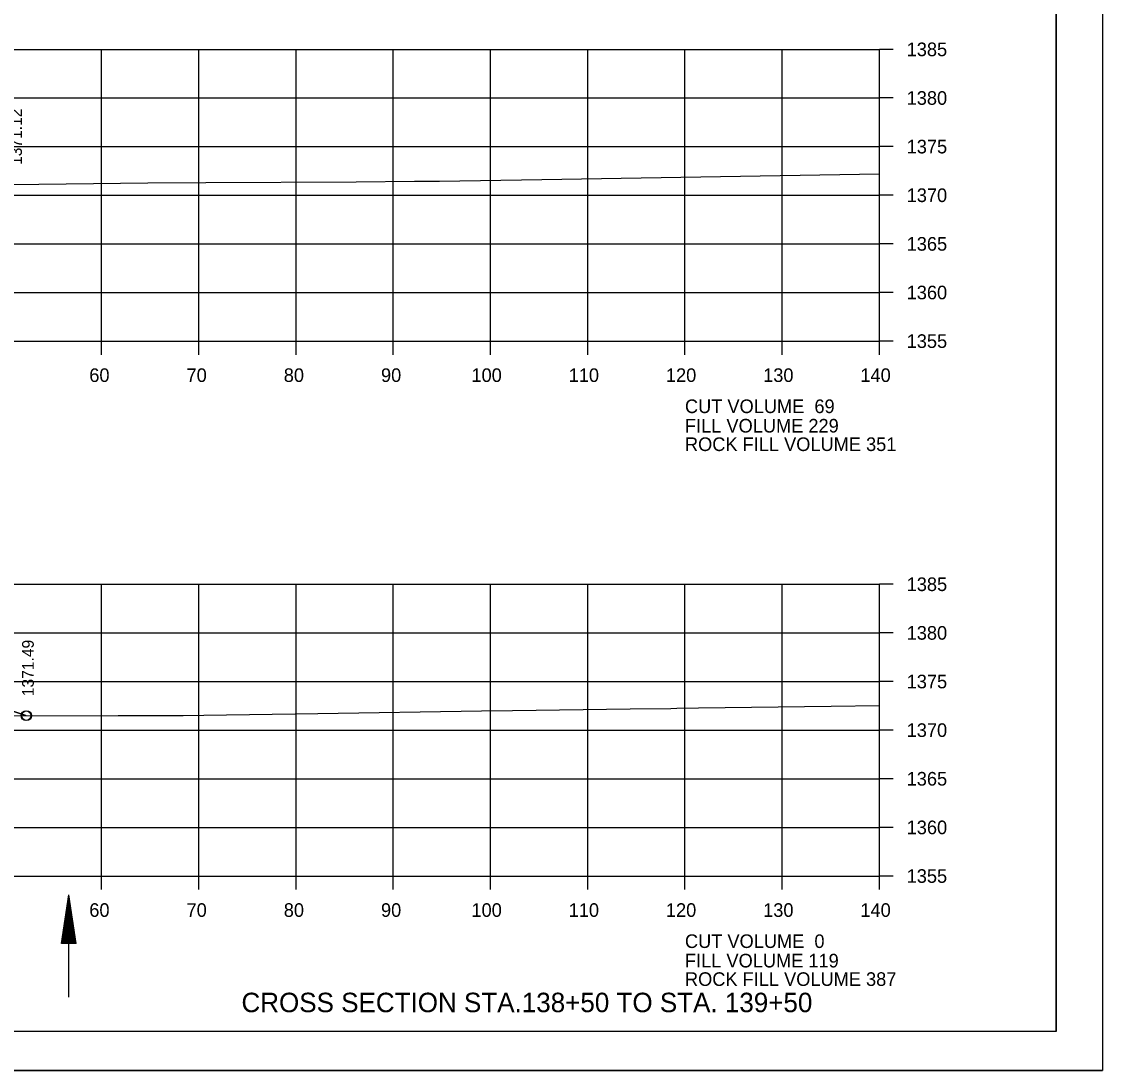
# Model space of a CAD drawing. Extents: x 1374311 to 1383814, y 384102 to 406278.
# Drawn here: x 1381680.4 to 1381791.6, y 389018 to 389125.9 of the extents above; entities that cross this region are included whole.
import ezdxf

# ---------------------------------------------------------------- set-up
doc = ezdxf.new("R2010")
doc.units = 0
for name, color, linetype in [('R_Axis', 7, 'Continuous'), ('R_Axis Annot', 7, 'Continuous'), ('R_Border', 7, 'Continuous'), ('R_Draft', 7, 'Continuous'), ('R_Exist Surface', 7, 'Continuous'), ('R_Fin Surface', 7, 'Continuous'), ('R_Grid', 7, 'Continuous'), ('R_No Plot', 7, 'Continuous'), ('R_Water', 7, 'Continuous'), ('R_Xsect Elev', 7, 'Continuous')]:
    doc.layers.add(name, color=color, linetype=linetype)

msp = doc.modelspace()

# ---------------------------------------------------------------- linework, layer by layer
at = {"layer": 'R_Axis'}
for p, q in [((1381768.66, 389093.02), (1381768.66, 389123.02)), ((1381770.06, 389123.02), (1381768.66, 389123.02)), ((1381770.06, 389118.02), (1381768.66, 389118.02)), ((1381770.06, 389113.02), (1381768.66, 389113.02)), ((1381770.06, 389108.02), (1381768.66, 389108.02)), ((1381770.06, 389103.02), (1381768.66, 389103.02)), ((1381770.06, 389098.02), (1381768.66, 389098.02)), ((1381488.66, 389093.02), (1381768.66, 389093.02)), ((1381688.66, 389091.62), (1381688.66, 389093.02)), ((1381698.66, 389091.62), (1381698.66, 389093.02)), ((1381708.66, 389091.62), (1381708.66, 389093.02)), ((1381718.66, 389091.62), (1381718.66, 389093.02)), ((1381728.66, 389091.62), (1381728.66, 389093.02)), ((1381738.66, 389091.62), (1381738.66, 389093.02)), ((1381748.66, 389091.62), (1381748.66, 389093.02)), ((1381758.66, 389091.62), (1381758.66, 389093.02)), ((1381768.66, 389091.62), (1381768.66, 389093.02)), ((1381770.06, 389093.02), (1381768.66, 389093.02)), ((1381768.66, 389038.02), (1381768.66, 389068.02)), ((1381770.06, 389068.02), (1381768.66, 389068.02)), ((1381770.06, 389063.02), (1381768.66, 389063.02)), ((1381770.06, 389058.02), (1381768.66, 389058.02)), ((1381770.06, 389053.02), (1381768.66, 389053.02)), ((1381770.06, 389048.02), (1381768.66, 389048.02)), ((1381770.06, 389043.02), (1381768.66, 389043.02)), ((1381488.66, 389038.02), (1381768.66, 389038.02)), ((1381688.66, 389036.62), (1381688.66, 389038.02)), ((1381698.66, 389036.62), (1381698.66, 389038.02)), ((1381708.66, 389036.62), (1381708.66, 389038.02)), ((1381718.66, 389036.62), (1381718.66, 389038.02)), ((1381728.66, 389036.62), (1381728.66, 389038.02)), ((1381738.66, 389036.62), (1381738.66, 389038.02)), ((1381748.66, 389036.62), (1381748.66, 389038.02)), ((1381758.66, 389036.62), (1381758.66, 389038.02)), ((1381768.66, 389036.62), (1381768.66, 389038.02)), ((1381770.06, 389038.02), (1381768.66, 389038.02))]:
    msp.add_line(p, q, dxfattribs=at)
at = {"layer": 'R_Border'}
for q in [(1381786.84, 389227.48), (1381470.66, 389022.02)]:
    msp.add_line((1381786.84, 389022.02), q, dxfattribs=at)
at = {"layer": 'R_Draft'}
for p, q in [((1381684.54, 389031.09), (1381685.29, 389036.09)), ((1381686.04, 389031.09), (1381685.29, 389036.09)), ((1381684.66, 389031.09), (1381685.29, 389035.26)), ((1381684.79, 389031.09), (1381685.29, 389034.4)), ((1381685.91, 389031.09), (1381685.29, 389035.26)), ((1381685.78, 389031.09), (1381685.29, 389034.4)), ((1381684.91, 389031.09), (1381685.29, 389033.56)), ((1381685.66, 389031.09), (1381685.29, 389033.56)), ((1381685.04, 389031.09), (1381685.29, 389032.72)), ((1381685.53, 389031.09), (1381685.29, 389032.72)), ((1381686.04, 389031.09), (1381684.54, 389031.09)), ((1381685.17, 389031.09), (1381685.29, 389031.88)), ((1381685.4, 389031.09), (1381685.29, 389031.88))]:
    msp.add_line(p, q, dxfattribs=at)
at = {"layer": 'R_Exist Surface'}
for points in [[(1381673.78, 389109.06), (1381693.41, 389109.31), (1381699.38, 389109.33), (1381714.83, 389109.41), (1381720.86, 389109.46), (1381723.4, 389109.47), (1381733.94, 389109.65), (1381768.66, 389110.23)], [(1381673.98, 389054.49), (1381690.37, 389054.52), (1381695.51, 389054.53), (1381697.07, 389054.54), (1381699.17, 389054.57), (1381710.89, 389054.74), (1381727.73, 389054.99), (1381730.91, 389055.04), (1381743.03, 389055.22), (1381747.2, 389055.26), (1381747.83, 389055.27), (1381750.06, 389055.31), (1381763.68, 389055.49), (1381768.66, 389055.56)]]:
    msp.add_lwpolyline(points, dxfattribs=at)
at = {"layer": 'R_Fin Surface'}
msp.add_lwpolyline([(1381570.5, 389051.42), (1381587.15, 389056.97), (1381592.15, 389056.87), (1381595.15, 389056.81), (1381595.65, 389056.81), (1381595.66, 389056.31), (1381596.66, 389056.33), (1381628.66, 389056.97), (1381660.66, 389057.44), (1381661.66, 389057.42), (1381661.67, 389057.92), (1381662.17, 389057.92), (1381665.17, 389057.98), (1381670.17, 389058.08), (1381680.89, 389054.51)], dxfattribs=at)
at = {"layer": 'R_Grid'}
for p, q in [((1381488.66, 389123.02), (1381768.66, 389123.02)), ((1381688.66, 389093.02), (1381688.66, 389123.02)), ((1381698.66, 389093.02), (1381698.66, 389123.02)), ((1381708.66, 389093.02), (1381708.66, 389123.02)), ((1381718.66, 389093.02), (1381718.66, 389123.02)), ((1381728.66, 389093.02), (1381728.66, 389123.02)), ((1381738.66, 389093.02), (1381738.66, 389123.02)), ((1381748.66, 389093.02), (1381748.66, 389123.02)), ((1381758.66, 389093.02), (1381758.66, 389123.02)), ((1381768.66, 389093.02), (1381768.66, 389123.02)), ((1381488.66, 389118.02), (1381768.66, 389118.02)), ((1381488.66, 389113.02), (1381768.66, 389113.02)), ((1381488.66, 389108.02), (1381768.66, 389108.02)), ((1381488.66, 389103.02), (1381768.66, 389103.02)), ((1381488.66, 389098.02), (1381768.66, 389098.02)), ((1381488.66, 389093.02), (1381768.66, 389093.02)), ((1381488.66, 389068.02), (1381768.66, 389068.02)), ((1381688.66, 389038.02), (1381688.66, 389068.02)), ((1381698.66, 389038.02), (1381698.66, 389068.02)), ((1381708.66, 389038.02), (1381708.66, 389068.02)), ((1381718.66, 389038.02), (1381718.66, 389068.02)), ((1381728.66, 389038.02), (1381728.66, 389068.02)), ((1381738.66, 389038.02), (1381738.66, 389068.02)), ((1381748.66, 389038.02), (1381748.66, 389068.02)), ((1381758.66, 389038.02), (1381758.66, 389068.02)), ((1381768.66, 389038.02), (1381768.66, 389068.02)), ((1381488.66, 389063.02), (1381768.66, 389063.02)), ((1381488.66, 389058.02), (1381768.66, 389058.02)), ((1381488.66, 389053.02), (1381768.66, 389053.02)), ((1381488.66, 389048.02), (1381768.66, 389048.02)), ((1381488.66, 389043.02), (1381768.66, 389043.02)), ((1381488.66, 389038.02), (1381768.66, 389038.02))]:
    msp.add_line(p, q, dxfattribs=at)
at = {"layer": 'R_No Plot'}
msp.add_line((1381458.26, 389018.04), (1381791.59, 389018.04), dxfattribs=at)
for points in [[(1381458.25, 389231.37), (1381791.59, 389231.37), (1381791.59, 389018.04), (1381458.25, 389018.04)], [(1381704.58, 389227.48), (1381704.58, 389217.6), (1381740.31, 389217.6), (1381740.31, 389214.68), (1381763.51, 389214.68), (1381763.51, 389191.46), (1381786.84, 389191.46), (1381786.84, 389022.02), (1381470.66, 389022.02), (1381470.66, 389227.48)]]:
    msp.add_lwpolyline(points, close=True, dxfattribs=at)
msp.add_lwpolyline([(1381673.98, 389054.49), (1381680.89, 389054.51), (1381670.17, 389058.08)], dxfattribs=at)
for centre in [(1381680.89, 389054.51), (1381680.96, 389054.5), (1381680.97, 389054.51)]:
    msp.add_circle(centre, 0.5, dxfattribs=at)
at = {"layer": 'R_Water'}
msp.add_line((1381685.29, 389025.58), (1381685.29, 389036.09), dxfattribs=at)

# ---------------------------------------------------------------- texts
at = {"layer": 'R_Axis Annot'}
for s, p in [('1385', (1381771.46, 389122.32)), ('1380', (1381771.46, 389117.32)), ('1375', (1381771.46, 389112.32)), ('1370', (1381771.46, 389107.32)), ('1365', (1381771.46, 389102.32)), ('1360', (1381771.46, 389097.32)), ('1355', (1381771.46, 389092.32)), ('60', (1381687.4, 389088.82)), ('70', (1381697.4, 389088.82)), ('80', (1381707.4, 389088.82)), ('90', (1381717.4, 389088.82)), ('100', (1381726.7, 389088.82)), ('110', (1381736.7, 389088.82)), ('120', (1381746.7, 389088.82)), ('130', (1381756.7, 389088.82)), ('140', (1381766.7, 389088.82)), ('CUT VOLUME  69', (1381748.66, 389085.62)), ('FILL VOLUME 229', (1381748.66, 389083.62)), ('ROCK FILL VOLUME 351', (1381748.66, 389081.72)), ('1385', (1381771.46, 389067.32)), ('1380', (1381771.46, 389062.32)), ('1375', (1381771.46, 389057.32)), ('1370', (1381771.46, 389052.32)), ('1365', (1381771.46, 389047.32)), ('1360', (1381771.46, 389042.32)), ('1355', (1381771.46, 389037.32)), ('60', (1381687.4, 389033.82)), ('70', (1381697.4, 389033.82)), ('80', (1381707.4, 389033.82)), ('90', (1381717.4, 389033.82)), ('100', (1381726.7, 389033.82)), ('110', (1381736.7, 389033.82)), ('120', (1381746.7, 389033.82)), ('130', (1381756.7, 389033.82)), ('140', (1381766.7, 389033.82)), ('CUT VOLUME  0', (1381748.66, 389030.62)), ('FILL VOLUME 119', (1381748.66, 389028.62)), ('ROCK FILL VOLUME 387', (1381748.66, 389026.72))]:
    msp.add_text(s, height=1.4, dxfattribs=at).set_placement(p)
at = {"layer": 'R_Draft'}
msp.add_text('CROSS SECTION STA.138+50 TO STA. 139+50', height=2, dxfattribs=at).set_placement((1381703.05, 389024.02))
at = {"layer": 'R_Xsect Elev'}
for s, p in [('1371.12', (1381680.47, 389111.13)), ('1371.49', (1381681.69, 389056.51))]:
    msp.add_text(s, height=1.2, rotation=90, dxfattribs=at).set_placement(p)

doc.saveas('drawing.dxf')
